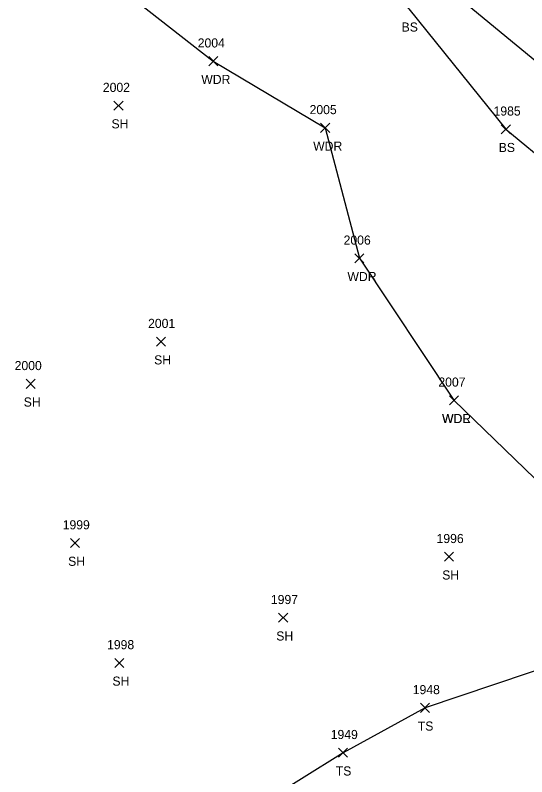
# Model space of a CAD drawing. Extents: x 1885914 to 1887218, y 756253 to 760620.
# Drawn here: x 1886275.2 to 1886387.4, y 759787.4 to 759954.5 of the extents above; entities that cross this region are included whole.
import ezdxf

# ---------------------------------------------------------------- set-up
doc = ezdxf.new("R2010")
doc.units = 0
for name, color, linetype in [('L_A', 7, 'Continuous'), ('L_I', 7, 'Continuous'), ('L_TIC', 7, 'Continuous'), ('LAWA', 7, 'Continuous'), ('LELB', 7, 'Continuous')]:
    doc.layers.add(name, color=color, linetype=linetype)

msp = doc.modelspace()

# ---------------------------------------------------------------- linework, layer by layer
at = {"layer": 'L_TIC'}
for points in [[(1886317.69, 759943.4), (1886319.69, 759945.4)], [(1886319.69, 759943.4), (1886317.69, 759945.4)], [(1886296.88, 759933.65), (1886298.88, 759935.65)], [(1886298.88, 759933.65), (1886296.88, 759935.65)], [(1886342.23, 759928.77), (1886344.23, 759930.77)], [(1886344.23, 759928.77), (1886342.23, 759930.77)], [(1886381.85, 759928.46), (1886383.85, 759930.46)], [(1886383.85, 759928.46), (1886381.85, 759930.46)], [(1886349.74, 759900.14), (1886351.74, 759902.14)], [(1886351.74, 759900.14), (1886349.74, 759902.14)], [(1886306.23, 759881.86), (1886308.23, 759883.86)], [(1886308.23, 759881.86), (1886306.23, 759883.86)], [(1886277.61, 759872.61), (1886279.61, 759874.61)], [(1886279.61, 759872.61), (1886277.61, 759874.61)], [(1886370.48, 759868.99), (1886372.48, 759870.99)], [(1886372.48, 759868.99), (1886370.48, 759870.99)], [(1886370.48, 759868.99), (1886372.48, 759870.99)], [(1886372.48, 759868.99), (1886370.48, 759870.99)], [(1886287.36, 759837.67), (1886289.36, 759839.67)], [(1886289.36, 759837.67), (1886287.36, 759839.67)], [(1886369.41, 759834.66), (1886371.41, 759836.66)], [(1886371.41, 759834.66), (1886369.41, 759836.66)], [(1886333.01, 759821.28), (1886335.01, 759823.28)], [(1886335.01, 759821.28), (1886333.01, 759823.28)], [(1886297.08, 759811.37), (1886299.08, 759813.37)], [(1886299.08, 759811.37), (1886297.08, 759813.37)], [(1886364.13, 759801.51), (1886366.13, 759803.51)], [(1886366.13, 759801.51), (1886364.13, 759803.51)], [(1886346.14, 759791.66), (1886348.14, 759793.66)], [(1886348.14, 759791.66), (1886346.14, 759793.66)]]:
    msp.add_lwpolyline(points, dxfattribs=at)
at = {"layer": 'LAWA'}
for points in [[(1886285.87, 759970.05), (1886318.69, 759944.4), (1886343.23, 759929.77), (1886350.74, 759901.14), (1886371.48, 759869.99)], [(1886420.25, 759558.57), (1886411.95, 759586.16), (1886411.02, 759591.73), (1886408.64, 759606.82), (1886405.28, 759619.96), (1886408.97, 759647.11), (1886409.34, 759668.38), (1886411.97, 759692.45), (1886411.89, 759715.23), (1886419.38, 759736.5), (1886421.95, 759756.23), (1886426.93, 759778.96), (1886430, 759796.54), (1886430.97, 759806.71), (1886430.75, 759808.98), (1886434.23, 759819.8), (1886435.82, 759833.71), (1886420.59, 759830.9), (1886400.43, 759842), (1886371.48, 759869.99)]]:
    msp.add_lwpolyline(points, dxfattribs=at)
at = {"layer": 'LELB'}
for points in [[(1886318.4, 760004.48), (1886336.83, 759980.36), (1886361.56, 759955.89), (1886382.85, 759929.46), (1886414.19, 759903.62), (1886402.13, 759873.85), (1886423.52, 759862.16), (1886432.91, 759869.01)], [(1886330.28, 760003.4), (1886339.73, 759985.11), (1886367.35, 759962.72), (1886393.37, 759941.16), (1886421.61, 759906.02), (1886432.44, 759885.61), (1886426.62, 759873.12), (1886408.74, 759874.79), (1886424.64, 759865.71), (1886432.91, 759869.01)], [(1886420.59, 759830.9), (1886395.58, 759812.74), (1886365.13, 759802.51), (1886347.14, 759792.66), (1886310.58, 759769.85), (1886294.3, 759752.2)]]:
    msp.add_lwpolyline(points, dxfattribs=at)

# ---------------------------------------------------------------- texts
at = {"layer": 'L_A'}
for s, p in [('BS', (1886360, 759950.89)), ('WDR', (1886316.05, 759939.4)), ('SH', (1886296.36, 759929.65)), ('WDR', (1886340.59, 759924.77)), ('BS', (1886381.29, 759924.46)), ('WDR', (1886348.11, 759896.14)), ('SH', (1886305.71, 759877.86)), ('SH', (1886277.1, 759868.61)), ('WDR', (1886368.84, 759864.99)), ('WDL', (1886368.89, 759864.99)), ('SH', (1886286.84, 759833.67)), ('SH', (1886368.9, 759830.66)), ('SH', (1886332.5, 759817.28)), ('SH', (1886296.56, 759807.37)), ('TS', (1886363.54, 759797.51)), ('TS', (1886345.55, 759787.66))]:
    msp.add_text(s, height=2, dxfattribs=at).set_placement(p)
at = {"layer": 'L_I'}
for s, p in [('2004', (1886315.27, 759947.4)), ('2002', (1886294.46, 759937.65)), ('2005', (1886339.81, 759932.77)), ('1985', (1886380.16, 759932.46)), ('2006', (1886347.27, 759904.14)), ('2001', (1886304.38, 759885.86)), ('2000', (1886275.11, 759876.61)), ('2007', (1886368.06, 759872.99)), ('2007', (1886368.06, 759872.99)), ('1999', (1886285.65, 759841.67)), ('1996', (1886367.66, 759838.66)), ('1997', (1886331.32, 759825.28)), ('1998', (1886295.38, 759815.37)), ('1948', (1886362.44, 759805.51)), ('1949', (1886344.44, 759795.66))]:
    msp.add_text(s, height=2, dxfattribs=at).set_placement(p)

doc.saveas('drawing.dxf')
